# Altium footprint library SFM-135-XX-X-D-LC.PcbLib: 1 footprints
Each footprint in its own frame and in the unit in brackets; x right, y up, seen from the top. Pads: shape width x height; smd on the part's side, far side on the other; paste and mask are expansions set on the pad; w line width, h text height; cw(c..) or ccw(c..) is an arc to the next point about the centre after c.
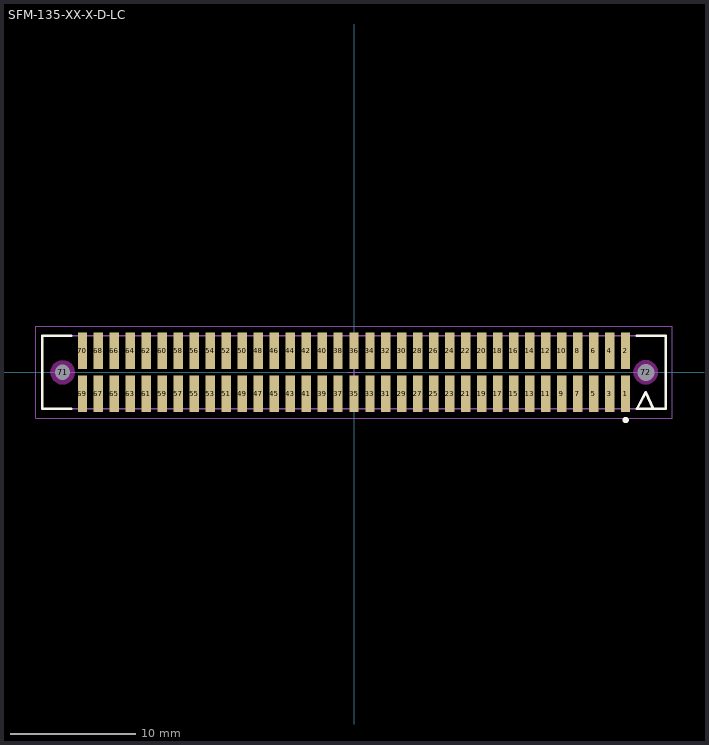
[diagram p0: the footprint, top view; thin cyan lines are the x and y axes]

## SFM-135-XX-X-D-LC [mm] "1.27mm pitch, 70 pin, micro socket strip; SMT"
height 4.57
pads (72):
  rect 0.75x2.9 smd mask+0: 1(21.59,-1.7) 2(21.59,1.7) 3(20.32,-1.7) 4(20.32,1.7) 5(19.05,-1.7) 6(19.05,1.7) 7(17.78,-1.7) 8(17.78,1.7) 9(16.51,-1.7) 10(16.51,1.7) 11(15.24,-1.7) 12(15.24,1.7) 13(13.97,-1.7) 14(13.97,1.7) 15(12.7,-1.7) 16(12.7,1.7) 17(11.43,-1.7) 18(11.43,1.7) 19(10.16,-1.7) 20(10.16,1.7) 21(8.89,-1.7) 22(8.89,1.7) 23(7.62,-1.7) 24(7.62,1.7) 25(6.35,-1.7) 26(6.35,1.7) 27(5.08,-1.7) 28(5.08,1.7) 29(3.81,-1.7) 30(3.81,1.7) 31(2.54,-1.7) 32(2.54,1.7) 33(1.27,-1.7) 34(1.27,1.7) 35(0,-1.7) 36(0,1.7) 37(-1.27,-1.7) 38(-1.27,1.7) 39(-2.54,-1.7) 40(-2.54,1.7) 41(-3.81,-1.7) 42(-3.81,1.7) 43(-5.08,-1.7) 44(-5.08,1.7) 45(-6.35,-1.7) 46(-6.35,1.7) 47(-7.62,-1.7) 48(-7.62,1.7) 49(-8.89,-1.7) 50(-8.89,1.7) 51(-10.16,-1.7) 52(-10.16,1.7) 53(-11.43,-1.7) 54(-11.43,1.7) 55(-12.7,-1.7) 56(-12.7,1.7) 57(-13.97,-1.7) 58(-13.97,1.7) 59(-15.24,-1.7) 60(-15.24,1.7) 61(-16.51,-1.7) 62(-16.51,1.7) 63(-17.78,-1.7) 64(-17.78,1.7) 65(-19.05,-1.7) 66(-19.05,1.7) 67(-20.32,-1.7) 68(-20.32,1.7) 69(-21.59,-1.7) 70(-21.59,1.7)
  round 1 hole 1.2 unplated mask+0: 71(-23.165,0)
  round 1 hole 1.35 unplated mask+0: 72(23.2,0)
Top Overlay:
  circle w0.25: c21.6,-3.8 r0.125
  lines w0.2: -22.5,-2.9 -24.8,-2.9 -24.8,2.9 -22.5,2.9 ; 22.5,2.9 24.8,2.9 24.8,-2.9 22.5,-2.9 23.2,-1.6 23.8,-2.9
Keep-Out Layer:
  pour cut-out: 24.167,0 24.134,0.252 24.037,0.486 23.882,0.687 23.681,0.842 23.447,0.939 23.195,0.972 22.944,0.939 22.709,0.842 22.508,0.687 22.353,0.486 22.256,0.252 22.223,0 22.256,-0.252 22.353,-0.486 22.508,-0.687 22.709,-0.842 22.944,-0.939 23.195,-0.972 23.447,-0.939 23.681,-0.842 23.882,-0.687 24.037,-0.486 24.134,-0.252
  pour cut-out: -22.204,0 -22.237,0.25 -22.334,0.484 -22.487,0.684 -22.688,0.838 -22.921,0.934 -23.171,0.967 -23.421,0.934 -23.655,0.838 -23.855,0.684 -24.009,0.484 -24.105,0.25 -24.138,0 -24.105,-0.25 -24.009,-0.484 -23.855,-0.684 -23.655,-0.838 -23.421,-0.934 -23.171,-0.967 -22.921,-0.934 -22.688,-0.838 -22.487,-0.684 -22.334,-0.484 -22.237,-0.25
Mechanical 12:
  lines w0.001: -24.8,-2.9 -24.8,2.9 24.8,2.9 24.8,-2.9 -24.8,-2.9
Mechanical 13:
  circle w0.1: c21.6,-3.8 r0.125
  lines w0.1: 22.5,-2.9 23.2,-1.6 23.8,-2.9 ; -24.8,-2.9 -24.8,2.9 24.8,2.9 24.8,-2.9 -24.8,-2.9
  text ".Designator" at 0.127,-0.127 h1.52
Mechanical 15:
  lines w0.05: -0.5,0 0.5,0 ; 0,-0.5 0,0.5 ; -25.3,-3.65 -25.3,3.65 25.3,3.65 25.3,-3.65 -25.3,-3.65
